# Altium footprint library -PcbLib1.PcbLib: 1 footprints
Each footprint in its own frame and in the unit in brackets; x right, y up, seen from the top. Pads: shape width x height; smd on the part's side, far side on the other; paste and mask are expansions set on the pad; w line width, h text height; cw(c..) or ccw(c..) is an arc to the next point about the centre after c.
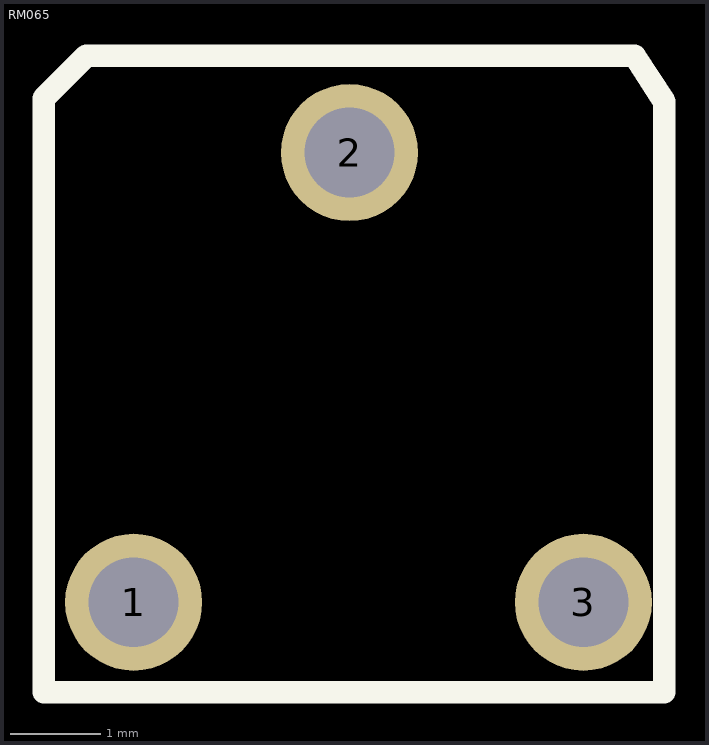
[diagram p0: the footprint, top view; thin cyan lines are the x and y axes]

## RM065 [mm]
pads (3):
  round 1.524 hole 1: 1(5.1,-7.6) 2(7.5,-2.6) 3(10.1,-7.6)
Top Overlay:
  lines w0.254: 4.1,-8.6 4.1,-1.996 4.572,-1.524 10.668,-1.524 11,-2.032 11,-8.6 4.1,-8.6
